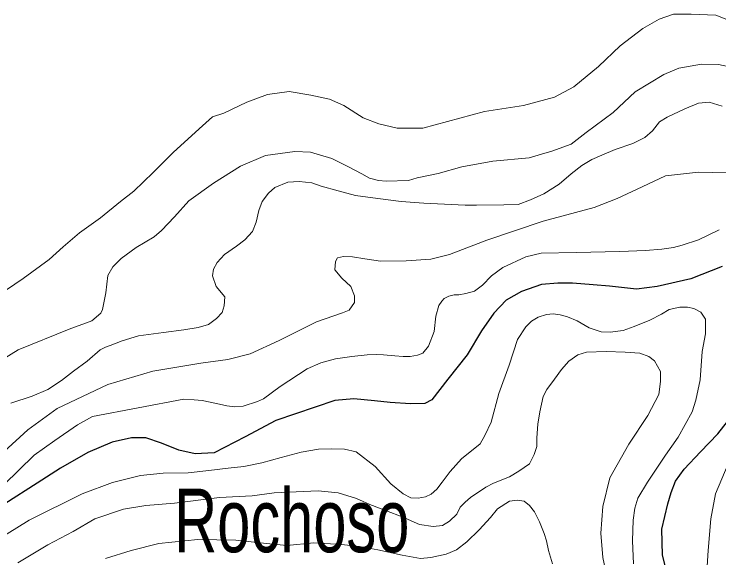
# Model space of a CAD drawing. Extents: x 474.5 to 500, y 7345.7 to 7373.4.
# Drawn here: x 484.682 to 485.568, y 7368.139 to 7368.823 of the extents above; entities that cross this region are included whole.
import ezdxf

# ---------------------------------------------------------------- set-up
doc = ezdxf.new("R2010")
doc.units = 0
doc.header["$LTSCALE"] = 0.032
doc.linetypes.add('SHORT_DASHED', pattern=[2.7, 1.5, -1.2])
for name, color, linetype, lineweight in [('1', 7, 'Continuous', 25), ('16', 7, 'SHORT_DASHED', 13), ('2', 7, 'Continuous', 13)]:
    doc.layers.add(name, color=color, linetype=linetype, lineweight=lineweight)
doc.layers.add('61', color=7, linetype='Continuous')

msp = doc.modelspace()

# ---------------------------------------------------------------- linework, layer by layer
at = {"layer": '1'}
for points in [[(485.5721, 7368.5058), (485.5325, 7368.4901), (485.4903, 7368.4806), (485.4644, 7368.4771), (485.4303, 7368.4812), (485.4099, 7368.4826), (485.384, 7368.4846), (485.3656, 7368.4846), (485.3451, 7368.4833), (485.3199, 7368.4744), (485.3008, 7368.4635), (485.2851, 7368.4472), (485.2695, 7368.4247), (485.2517, 7368.3947), (485.2272, 7368.364), (485.2074, 7368.3381), (485.1986, 7368.3333), (485.1804, 7368.3329), (485.155, 7368.3347), (485.1352, 7368.3367), (485.1093, 7368.3395), (485.0854, 7368.3374), (485.0112, 7368.3122), (484.9725, 7368.2915), (484.9335, 7368.2713), (484.9096, 7368.27), (484.8892, 7368.2747), (484.8674, 7368.2836), (484.8476, 7368.2904), (484.8299, 7368.2904), (484.8053, 7368.285), (484.7747, 7368.272), (484.7406, 7368.2522), (484.7113, 7368.2332), (484.6704, 7368.2073)], [(485.5714, 7367.8924), (485.5571, 7367.9237), (485.5312, 7367.9653), (485.5237, 7367.983), (485.5216, 7367.9953), (485.5189, 7368.0532), (485.5134, 7368.0764), (485.5066, 7368.1044), (485.4971, 7368.1425), (485.4964, 7368.1752), (485.5039, 7368.2073), (485.508, 7368.2216), (485.5134, 7368.2359), (485.5243, 7368.2509), (485.5448, 7368.2727), (485.5666, 7368.2952), (485.5789, 7368.3109)]]:
    msp.add_lwpolyline(points, dxfattribs=at)
at = {"layer": '16'}
msp.add_lwpolyline([(485.5989, 7368.8077), (485.5641, 7368.8219), (485.5331, 7368.8232), (485.5111, 7368.8232), (485.493, 7368.8167), (485.4724, 7368.8051), (485.4439, 7368.7831), (485.4168, 7368.7573), (485.3858, 7368.7315), (485.3613, 7368.7186), (485.3225, 7368.7082), (485.2734, 7368.7005), (485.196, 7368.6798), (485.1637, 7368.6798), (485.1404, 7368.685), (485.121, 7368.6927), (485.0965, 7368.7082), (485.0784, 7368.716), (485.0552, 7368.7211), (485.0278, 7368.7257), (485.0007, 7368.722), (484.9746, 7368.7126), (484.9456, 7368.6986), (484.9316, 7368.6939), (484.9148, 7368.679), (484.8821, 7368.6491), (484.8569, 7368.6239), (484.8326, 7368.6005), (484.8158, 7368.5875), (484.7906, 7368.5669), (484.7644, 7368.5482), (484.7439, 7368.5305), (484.7261, 7368.5146), (484.6935, 7368.4905), (484.6514, 7368.4623)], dxfattribs=at)
at = {"layer": '2'}
for points in [[(485.0547, 7368.6495), (485.0817, 7368.6415), (485.1016, 7368.6316), (485.1191, 7368.6223), (485.1287, 7368.617), (485.14, 7368.614), (485.1499, 7368.6131), (485.1779, 7368.6141), (485.1888, 7368.6171), (485.2153, 7368.6227), (485.2451, 7368.631), (485.2838, 7368.6383), (485.3296, 7368.6426), (485.3451, 7368.6472), (485.358, 7368.6509), (485.3822, 7368.6598), (485.4012, 7368.6743), (485.435, 7368.6994), (485.4628, 7368.7253), (485.4989, 7368.7471), (485.5174, 7368.7551), (485.5462, 7368.7601), (485.5674, 7368.7597), (485.5967, 7368.7537)], [(485.5722, 7368.7072), (485.5559, 7368.7125), (485.5422, 7368.7111), (485.525, 7368.7041), (485.503, 7368.6935), (485.4933, 7368.6878), (485.4845, 7368.6763), (485.4748, 7368.6679), (485.4598, 7368.6604), (485.4377, 7368.6529), (485.421, 7368.6459), (485.4082, 7368.6402), (485.3959, 7368.6327), (485.3822, 7368.6221), (485.3672, 7368.6093), (485.3478, 7368.597), (485.3311, 7368.5895), (485.3156, 7368.5837), (485.2976, 7368.5833), (485.2632, 7368.5828), (485.2491, 7368.5828), (485.2231, 7368.5842), (485.197, 7368.5855), (485.1688, 7368.5873), (485.1393, 7368.5912), (485.1111, 7368.5952), (485.0895, 7368.6009), (485.0683, 7368.6067), (485.0564, 7368.6111), (485.0406, 7368.6128), (485.0264, 7368.6119), (485.0101, 7368.6049), (485.0018, 7368.5978), (484.9938, 7368.5873), (484.9899, 7368.5762)], [(484.6297, 7368.3654), (484.6874, 7368.4008), (484.7516, 7368.4269), (484.7798, 7368.4372), (484.7911, 7368.4472), (484.7934, 7368.4515), (484.7977, 7368.4727), (484.8001, 7368.4945), (484.8061, 7368.5054), (484.8167, 7368.516), (484.8355, 7368.5296), (484.8581, 7368.5429), (484.8673, 7368.5511), (484.8836, 7368.568), (484.902, 7368.5882), (484.9328, 7368.6107), (484.9666, 7368.6319), (484.9981, 7368.6455), (485.0349, 7368.6504), (485.0547, 7368.6495)], [(485.5953, 7368.6232), (485.5424, 7368.6245), (485.5007, 7368.6196), (485.4715, 7368.6061), (485.4401, 7368.5913), (485.4113, 7368.5801), (485.3472, 7368.5626), (485.2763, 7368.5388), (485.2296, 7368.5209), (485.2058, 7368.515), (485.1748, 7368.5128), (485.1425, 7368.5123), (485.1228, 7368.5155), (485.1075, 7368.5177), (485.0963, 7368.5182), (485.0887, 7368.5168), (485.086, 7368.5119), (485.0851, 7368.5016), (485.0941, 7368.4912), (485.1053, 7368.4805), (485.1102, 7368.4688), (485.1098, 7368.4603), (485.1035, 7368.4509), (485.095, 7368.4473), (485.0622, 7368.436), (485.0155, 7368.4127), (484.9787, 7368.3961), (484.9509, 7368.3889), (484.9168, 7368.384), (484.8566, 7368.3741), (484.8001, 7368.3575), (484.7364, 7368.327), (484.6996, 7368.3005), (484.6345, 7368.2413)], [(484.9899, 7368.5762), (484.9863, 7368.5617), (484.9819, 7368.5498), (484.9722, 7368.5392), (484.9616, 7368.5313), (484.9467, 7368.5207), (484.9374, 7368.5106), (484.933, 7368.5022), (484.9317, 7368.4938), (484.9361, 7368.4806), (484.9471, 7368.4678), (484.9463, 7368.4563), (484.9436, 7368.448), (484.9365, 7368.4405), (484.9264, 7368.433), (484.9136, 7368.429), (484.8955, 7368.4259), (484.87, 7368.4228), (484.8387, 7368.4184), (484.8179, 7368.4122), (484.8029, 7368.4065), (484.7972, 7368.4043), (484.7902, 7368.4008), (484.7739, 7368.3867), (484.7567, 7368.3739), (484.7417, 7368.3624), (484.7245, 7368.351), (484.7051, 7368.3426), (484.6782, 7368.3338)], [(485.5684, 7368.5519), (485.5422, 7368.5392), (485.5218, 7368.5325), (485.5107, 7368.5295), (485.4963, 7368.5275), (485.4759, 7368.5258), (485.4435, 7368.5248), (485.3885, 7368.5235), (485.3444, 7368.5225), (485.3253, 7368.5181), (485.2965, 7368.5045), (485.2821, 7368.4938), (485.2707, 7368.4824), (485.2607, 7368.4747), (485.25, 7368.4717), (485.2413, 7368.4703), (485.2353, 7368.47), (485.2286, 7368.4683), (485.2229, 7368.4656), (485.2196, 7368.462), (485.2159, 7368.4566), (485.2122, 7368.4432), (485.2102, 7368.4241), (485.2032, 7368.4057), (485.1957, 7368.3967), (485.1893, 7368.3943), (485.18, 7368.3926), (485.1713, 7368.3926), (485.1606, 7368.3933), (485.1465, 7368.3947), (485.1375, 7368.395), (485.1258, 7368.3947), (485.1067, 7368.3926), (485.086, 7368.3896), (485.0678, 7368.3846), (485.0505, 7368.3769), (485.0164, 7368.3548), (484.9956, 7368.3395), (484.9883, 7368.3358), (484.9702, 7368.3301), (484.9598, 7368.3294), (484.9495, 7368.3304), (484.9364, 7368.3334), (484.9184, 7368.3374), (484.9087, 7368.3381), (484.8956, 7368.3388), (484.7807, 7368.317), (484.7618, 7368.3066), (484.7334, 7368.2869), (484.7076, 7368.2685)], [(485.4606, 7368.1319), (485.4593, 7368.1606), (485.4602, 7368.1868), (485.4623, 7368.2018), (485.4662, 7368.2142), (485.4782, 7368.2344), (485.5009, 7368.2683), (485.5168, 7368.291), (485.5344, 7368.3231), (485.5391, 7368.3377), (485.5442, 7368.363), (485.5468, 7368.399), (485.5511, 7368.4209), (485.5511, 7368.4394), (485.5451, 7368.4484), (485.5365, 7368.4531), (485.5284, 7368.4544), (485.5189, 7368.4544), (485.5056, 7368.4518), (485.4958, 7368.4458), (485.4812, 7368.4381), (485.4615, 7368.4304), (485.4477, 7368.4252), (485.4314, 7368.4231), (485.4199, 7368.4235), (485.4049, 7368.4286), (485.3898, 7368.4376), (485.3778, 7368.4424), (485.3684, 7368.4449), (485.3598, 7368.4462), (485.3513, 7368.4454), (485.341, 7368.4419), (485.3324, 7368.4368), (485.3255, 7368.4299), (485.3148, 7368.4141), (485.3045, 7368.3815), (485.2912, 7368.3459), (485.2818, 7368.3098), (485.2736, 7368.2931), (485.2681, 7368.2828), (485.2445, 7368.264), (485.2303, 7368.2481), (485.22, 7368.2344), (485.2136, 7368.2258), (485.2063, 7368.2194), (485.1994, 7368.2159), (485.19, 7368.2142), (485.181, 7368.2146), (485.1711, 7368.2198), (485.1557, 7368.2322), (485.136, 7368.2541), (485.112, 7368.2725), (485.0974, 7368.276), (485.0815, 7368.2764), (485.0648, 7368.276), (485.0429, 7368.2721), (485.018, 7368.2657), (484.9936, 7368.2588), (484.9709, 7368.2541), (484.9511, 7368.252), (484.9271, 7368.249), (484.901, 7368.2464)], [(485.4262, 7368.12), (485.4221, 7368.1398), (485.4194, 7368.1705), (485.4221, 7368.2039), (485.431, 7368.24), (485.4548, 7368.2822), (485.4787, 7368.3183), (485.4923, 7368.3449), (485.4944, 7368.3613), (485.4944, 7368.3736), (485.4869, 7368.3872), (485.48, 7368.3926), (485.4685, 7368.3967), (485.4501, 7368.3981), (485.4262, 7368.3988), (485.4017, 7368.3981), (485.3908, 7368.3947), (485.3792, 7368.3865), (485.3703, 7368.3763), (485.3615, 7368.364), (485.3519, 7368.3511), (485.3472, 7368.3422), (485.3431, 7368.3231), (485.3403, 7368.3074), (485.339, 7368.2904), (485.339, 7368.2795), (485.3356, 7368.2693), (485.3301, 7368.2577), (485.3165, 7368.2482), (485.3049, 7368.2413), (485.2845, 7368.2332), (485.2749, 7368.2284), (485.2558, 7368.2154), (485.249, 7368.2093), (485.2429, 7368.2032), (485.2388, 7368.1943), (485.2292, 7368.1855), (485.2204, 7368.18), (485.2088, 7368.1786), (485.1918, 7368.1814), (485.17, 7368.1909), (485.1502, 7368.1984), (485.1291, 7368.2066), (485.1127, 7368.2141), (485.0895, 7368.2209), (485.0643, 7368.2236), (485.0091, 7368.2209), (484.9812, 7368.2175), (484.9403, 7368.2154), (484.8837, 7368.2079), (484.8476, 7368.2052), (484.8197, 7368.2004), (484.7835, 7368.1882), (484.7563, 7368.1725), (484.7245, 7368.1556), (484.687, 7368.1332)], [(484.7076, 7368.2685), (484.6692, 7368.2313)], [(485.5758, 7367.9946), (485.5658, 7368.0187), (485.5594, 7368.0324), (485.5524, 7368.0612), (485.5509, 7368.0958), (485.5545, 7368.1484), (485.5579, 7368.1885), (485.5636, 7368.22), (485.5795, 7368.2577)], [(484.901, 7368.2464), (484.8697, 7368.246), (484.8409, 7368.2429), (484.8058, 7368.2339), (484.7676, 7368.2198), (484.7011, 7368.1868), (484.6608, 7368.1619)], [(485.3587, 7368.1316), (485.354, 7368.1486), (485.3512, 7368.1609), (485.3485, 7368.1698), (485.3424, 7368.1848), (485.3362, 7368.197), (485.3301, 7368.2052), (485.3233, 7368.2107), (485.3144, 7368.212), (485.3049, 7368.2107), (485.2899, 7368.2011), (485.281, 7368.1902), (485.2667, 7368.1745), (485.2511, 7368.1596), (485.2381, 7368.1493), (485.2252, 7368.1439), (485.2061, 7368.1398), (485.1931, 7368.1384), (485.17, 7368.1425), (485.1393, 7368.1493), (485.1161, 7368.1534), (485.0936, 7368.1561), (485.0589, 7368.1582), (485.0248, 7368.1548), (484.9996, 7368.1575), (484.9607, 7368.1616), (484.913, 7368.1623), (484.864, 7368.1575), (484.8292, 7368.1486), (484.7972, 7368.1384)]]:
    msp.add_lwpolyline(points, dxfattribs=at)

# ---------------------------------------------------------------- texts
at = {"layer": '61', "width": 0.7}
msp.add_text('Rochoso', height=0.08, dxfattribs=at).set_placement((484.8834, 7368.1464))

doc.saveas('drawing.dxf')
